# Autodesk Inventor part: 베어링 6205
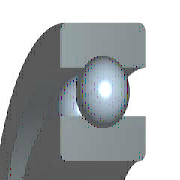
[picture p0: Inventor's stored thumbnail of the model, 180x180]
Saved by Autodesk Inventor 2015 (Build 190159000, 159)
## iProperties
Created: 2015-10
Part Number: 베어링 6205
Material: 강, 연강
Description: 깊은 그루브 볼 베어링
Document SubType Name: Modeling
Standard: KS B 2023
Designer: mdu
Standards Organization: KS
Language: ko-KR
Size Designation: 6205 - 25 x 52 x 15
Categories: <MemberInstance><Categories><Category DisplayName="샤프트 부품" InternalName="7f7aeb1f-a693-4053-b835-cee3144e0d98" Mnemonic="SHFT"><Category DisplayName="베어링" Inter
Density: 7.85 g/cm^3
Appearance: 강철
Mass: 129.378 g
Surface Area: 107.326 cm^2
Volume: 16.4813 cm^3
IsCustomPart: 1
Author: mdu
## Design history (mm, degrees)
sketch "스케치" dims "d0" = 7.02 (= -0.26 x WD + 0.26 x BD)
  geometry: L1 (3.99, 19.25)-(11.01, 19.25); L2 (7.5, 19.25)-(7.5, 15.74); L3 (7.5, 19.25)-(7.5, 22.76); L4 (4.892, 16.901)-(0, 16.901); L5 (0, 12.5)-(15, 12.5); L6 (4.892, 21.599)-(0, 21.599); L7 (0, 26)-(15, 26); L8 (15, 12.5)-(15, 16.901); L9 (10.108, 16.901)-(15, 16.901); L10 (10.108, 21.599)-(15, 21.599); L11 (15, 26)-(15, 21.599); L12 (-1.4, 0)-(8.4, 0) reference; L13 (0, -0.3)-(0, 5.3) reference
  constraints: 22 end point, 4 point on line, 2 collinear, 2 perpendicular, 2 symmetric about line, 1 midpoint, 1 parallel, 14 other
  dimensions: "d9" = 25 diameter of L5 L12 (= WD); "d11" = 52 diameter of L7 L12 (= BD); "d12" = 15 distance between parallel lines of L8 L13 (= KB); "d13" = 33.802 diameter of L9 L12 (= 0.326 x BD + 0.674 x WD)
revolve "본체" stored, may be unused: angle "d6" = 90 deg
revolve "볼" stored, may be unused: angle "d7" = 90 deg
pattern_circular "IDS_ARRAYBALL[SIMPL:T]" dims angle "d3" = 360 deg
body "Solid1"
fillet "모깎기1" dims "d1" = 1 (= KRS)
other parameters: "WD" = 25 [user parameter; used in 5 equation terms], "BD" = 52 [user parameter; used in 5 equation terms], "KB" = 15 [user parameter; used in 1 equation term], "KRS" = 1 [user parameter; used in 1 equation term], "d4" = 0, "d5" = 0, "d8" = 0, "d14" = 0, "d15" = 0, "BBA" = 0 [user parameter], "BC0" = 7800000 [user parameter], "BC" = 1.4e+07 [user parameter], "BR" = 26 (= 0.5 x BD) [user parameter], "WR" = 12.5 (= 0.5 x WD) [user parameter]
